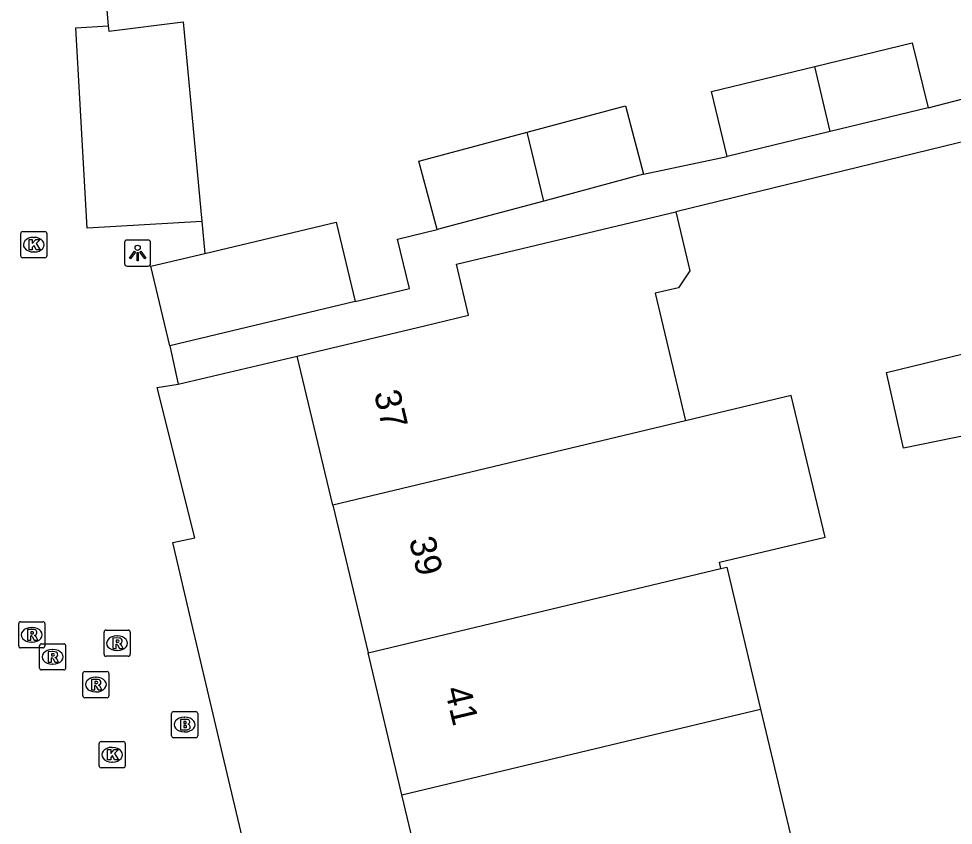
# Model space of a CAD drawing. Extents: x 158038 to 159242, y 380133 to 381214.
# Drawn here: x 158439.3 to 158475.04, y 381055.11 to 381085.97 of the extents above; entities that cross this region are included whole.
import ezdxf

# ---------------------------------------------------------------- set-up
doc = ezdxf.new("R2010")
doc.units = 0
for name, color, linetype in [('IMGEO_Brandkraan', 7, 'Continuous'), ('IMGEO_Kolk', 7, 'Continuous'), ('IMGEO_Lichtpunt', 7, 'Continuous'), ('IMGEO_Pand', 7, 'Continuous'), ('IMGEO_Pand_nummerreeks', 7, 'Continuous'), ('IMGEO_Parkeervlak_open', 7, 'Continuous'), ('IMGEO_Rioolput', 7, 'Continuous'), ('IMGEO_Voetpad_open', 7, 'Continuous')]:
    doc.layers.add(name, color=color, linetype=linetype)

msp = doc.modelspace()

# ---------------------------------------------------------------- linework, layer by layer
at = {"layer": 'IMGEO_Brandkraan'}
for p, q in [((158445.141, 381058.539), (158445.141, 381059.391)), ((158445.216, 381059.465), (158446.068, 381059.465)), ((158445.629, 381059.245), (158445.654, 381059.245)), ((158446.142, 381059.391), (158446.142, 381058.539)), ((158446.068, 381058.465), (158445.216, 381058.465)), ((158445.652, 381058.685), (158445.627, 381058.685))]:
    msp.add_line(p, q, dxfattribs=at)
for points in [[(158445.141, 381058.539), (158445.141, 381059.391)], [(158445.216, 381059.465), (158446.068, 381059.465)], [(158446.142, 381059.391), (158446.142, 381058.539)], [(158445.489, 381059.165), (158445.489, 381058.765), (158445.702, 381058.765)], [(158445.72, 381059.165), (158445.489, 381059.165)], [(158445.668, 381059.084), (158445.614, 381059.084), (158445.614, 381059.008)], [(158445.614, 381059.008), (158445.667, 381059.008)], [(158445.676, 381058.932), (158445.614, 381058.932), (158445.614, 381058.851)], [(158445.614, 381058.851), (158445.676, 381058.851)], [(158446.068, 381058.465), (158445.216, 381058.465)]]:
    msp.add_lwpolyline(points, dxfattribs=at)
for centre, radius, start, end in [((158445.218, 381059.389), 0.0765, 91.552, 178.448), ((158445.218, 381059.389), 0.0765, 91.552, 178.448), ((158446.066, 381059.389), 0.0765, 1.552, 88.448), ((158446.066, 381059.389), 0.0765, 1.552, 88.448), ((158445.669, 381059.046), 0.0379, 267.8285, 90.9355), ((158445.677, 381058.891), 0.0404, 269.8759, 90.5077), ((158445.724, 381059.02), 0.145, 59.4692, 91.5367), ((158445.749, 381059.067), 0.0922, 285.5137, 58.1501), ((158445.754, 381058.875), 0.105, 301.3115, 78.989), ((158445.218, 381058.541), 0.0765, 181.552, 268.448), ((158445.218, 381058.541), 0.0765, 181.552, 268.448), ((158445.708, 381059.016), 0.251, 268.6676, 293.5347), ((158446.066, 381058.541), 0.0765, 271.552, 358.448), ((158446.066, 381058.541), 0.0765, 271.552, 358.448)]:
    msp.add_arc(centre, radius, start, end, dxfattribs=at)
for centre, major_axis, ratio, start_param, end_param in [((158445.628, 381058.965), (-0.387, 0.002), 0.722429, 4.712389, 7.853982), ((158445.653, 381058.965), (-0.39, 0.002), 0.717154, 1.570796, 4.712389)]:
    msp.add_ellipse(centre, major_axis=major_axis, ratio=ratio, start_param=start_param, end_param=end_param, dxfattribs=at)
at = {"layer": 'IMGEO_Kolk'}
for p, q in [((158439.448, 381077.824), (158440.3, 381077.824)), ((158439.373, 381076.898), (158439.373, 381077.75)), ((158439.861, 381077.604), (158439.886, 381077.604)), ((158440.374, 381077.75), (158440.374, 381076.898)), ((158439.884, 381077.044), (158439.859, 381077.044)), ((158440.3, 381076.824), (158439.448, 381076.824)), ((158442.37, 381057.388), (158442.37, 381058.24)), ((158442.445, 381058.314), (158443.297, 381058.314)), ((158443.371, 381058.24), (158443.371, 381057.388)), ((158442.858, 381058.094), (158442.883, 381058.094)), ((158442.881, 381057.534), (158442.856, 381057.534)), ((158443.297, 381057.314), (158442.445, 381057.314))]:
    msp.add_line(p, q, dxfattribs=at)
for points in [[(158439.448, 381077.824), (158440.3, 381077.824)], [(158439.373, 381076.898), (158439.373, 381077.75)], [(158439.694, 381077.524), (158439.817, 381077.524), (158439.817, 381077.373), (158439.947, 381077.524), (158440.111, 381077.524), (158439.965, 381077.373), (158440.118, 381077.124), (158439.966, 381077.124), (158439.881, 381077.288), (158439.817, 381077.221), (158439.817, 381077.124), (158439.694, 381077.124), (158439.694, 381077.524)], [(158440.374, 381077.75), (158440.374, 381076.898)], [(158440.3, 381076.824), (158439.448, 381076.824)], [(158442.37, 381057.388), (158442.37, 381058.24)], [(158442.445, 381058.314), (158443.297, 381058.314)], [(158443.371, 381058.24), (158443.371, 381057.388)], [(158442.691, 381058.014), (158442.814, 381058.014), (158442.814, 381057.863), (158442.944, 381058.014), (158443.108, 381058.014), (158442.962, 381057.863), (158443.115, 381057.614), (158442.963, 381057.614), (158442.878, 381057.778), (158442.814, 381057.711), (158442.814, 381057.614), (158442.691, 381057.614), (158442.691, 381058.014)], [(158443.297, 381057.314), (158442.445, 381057.314)]]:
    msp.add_lwpolyline(points, dxfattribs=at)
for centre, start, end in [((158439.45, 381077.748), 91.552, 178.448), ((158439.45, 381077.748), 91.552, 178.448), ((158440.298, 381077.748), 1.552, 88.448), ((158440.298, 381077.748), 1.552, 88.448), ((158439.45, 381076.9), 181.552, 268.448), ((158439.45, 381076.9), 181.552, 268.448), ((158440.298, 381076.9), 271.552, 358.448), ((158440.298, 381076.9), 271.552, 358.448), ((158442.447, 381058.238), 91.552, 178.448), ((158442.447, 381058.238), 91.552, 178.448), ((158443.295, 381058.238), 1.552, 88.448), ((158443.295, 381058.238), 1.552, 88.448), ((158442.447, 381057.39), 181.552, 268.448), ((158442.447, 381057.39), 181.552, 268.448), ((158443.295, 381057.39), 271.552, 358.448), ((158443.295, 381057.39), 271.552, 358.448)]:
    msp.add_arc(centre, 0.0765, start, end, dxfattribs=at)
for centre, major_axis, ratio, start_param, end_param in [((158439.86, 381077.324), (-0.387, 0.002), 0.722429, 4.712389, 7.853982), ((158439.885, 381077.324), (-0.39, 0.002), 0.717154, 1.570796, 4.712389), ((158442.857, 381057.814), (-0.387, 0.002), 0.722429, 4.712389, 7.853982), ((158442.882, 381057.814), (-0.39, 0.002), 0.717154, 1.570796, 4.712389)]:
    msp.add_ellipse(centre, major_axis=major_axis, ratio=ratio, start_param=start_param, end_param=end_param, dxfattribs=at)
at = {"layer": 'IMGEO_Lichtpunt'}
for p, q in [((158443.346, 381077.407), (158443.346, 381076.6)), ((158443.346, 381077.407), (158443.346, 381076.6)), ((158444.248, 381077.502), (158443.44, 381077.502)), ((158444.248, 381077.502), (158443.44, 381077.502)), ((158444.342, 381076.6), (158444.342, 381077.407)), ((158444.342, 381076.6), (158444.342, 381077.407)), ((158443.44, 381076.506), (158444.248, 381076.506)), ((158443.44, 381076.506), (158444.248, 381076.506))]:
    msp.add_line(p, q, dxfattribs=at)
for points in [[(158443.72, 381077.071), (158443.759, 381077.043), (158443.571, 381076.781), (158443.533, 381076.808), (158443.72, 381077.071)], [(158443.932, 381077.043), (158443.97, 381077.07), (158444.157, 381076.808), (158444.118, 381076.78), (158443.932, 381077.043)], [(158443.822, 381077.023), (158443.869, 381077.023), (158443.869, 381076.701), (158443.822, 381076.701), (158443.822, 381077.023)]]:
    msp.add_lwpolyline(points, dxfattribs=at)
msp.add_circle((158443.845, 381077.205), 0.0994, dxfattribs=at)
for centre, start, end in [((158443.44, 381077.407), 90, 180), ((158443.44, 381077.407), 90, 180), ((158444.248, 381077.407), 0, 90), ((158444.248, 381077.407), 0, 90), ((158443.44, 381076.6), 180, 270), ((158443.44, 381076.6), 180, 270), ((158444.248, 381076.6), 270, 0), ((158444.248, 381076.6), 270, 360)]:
    msp.add_arc(centre, 0.0946, start, end, dxfattribs=at)
at = {"layer": 'IMGEO_Pand'}
for points in [[(158469.74, 381084.142), (158473.474, 381085.047), (158474.077, 381082.564)], [(158466.391, 381080.7), (158465.789, 381083.183), (158469.74, 381084.142)], [(158470.334, 381081.656), (158469.74, 381084.142)], [(158458.745, 381081.625), (158462.498, 381082.631), (158463.199, 381080.018)], [(158474.077, 381082.564), (158470.334, 381081.656)], [(158455.306, 381077.901), (158454.605, 381080.514), (158458.745, 381081.625)], [(158459.375, 381078.993), (158458.745, 381081.625)], [(158470.334, 381081.656), (158466.391, 381080.7)], [(158463.199, 381080.018), (158459.375, 381078.993)], [(158459.375, 381078.993), (158455.306, 381077.901)], [(158449.949, 381073.061), (158454.813, 381074.222), (158456.505, 381074.626), (158456.038, 381076.581), (158464.428, 381078.584)], [(158464.428, 381078.584), (158464.968, 381076.318), (158464.527, 381075.676), (158463.639, 381075.464), (158464.804, 381070.586)], [(158446.413, 381076.99), (158451.439, 381078.19), (158452.165, 381075.147)], [(158445.073, 381073.454), (158444.346, 381076.497), (158446.413, 381076.99)], [(158452.165, 381075.147), (158445.073, 381073.454)], [(158479.975, 381069.848), (158477.836, 381069.413), (158477.569, 381070.449), (158473.135, 381069.546), (158472.493, 381072.44), (158476.891, 381073.501)], [(158451.311, 381067.355), (158449.949, 381073.061)], [(158466.154, 381064.935), (158466.096, 381065.176), (158470.135, 381066.141), (158468.842, 381071.553), (158464.804, 381070.586)], [(158464.804, 381070.586), (158451.311, 381067.355)], [(158451.311, 381067.355), (158452.657, 381061.714)], [(158452.657, 381061.714), (158466.154, 381064.935)], [(158466.154, 381064.935), (158466.377, 381064.988), (158467.674, 381059.556)], [(158453.954, 381056.282), (158452.657, 381061.714)], [(158453.954, 381056.282), (158462.534, 381058.328), (158467.674, 381059.556)], [(158467.674, 381059.556), (158469.024, 381053.9)], [(158457.583, 381051.17), (158455.304, 381050.627), (158453.954, 381056.282)]]:
    msp.add_lwpolyline(points, dxfattribs=at)
at = {"layer": 'IMGEO_Parkeervlak_open'}
msp.add_lwpolyline([(158442.724, 381085.689), (158442.741, 381085.485), (158445.587, 381085.853), (158446.299, 381078.211)], dxfattribs=at)
at = {"layer": 'IMGEO_Rioolput'}
for p, q in [((158439.295, 381061.975), (158439.295, 381062.827)), ((158439.37, 381062.901), (158440.222, 381062.901)), ((158440.296, 381062.827), (158440.296, 381061.975)), ((158439.783, 381062.681), (158439.808, 381062.681)), ((158442.56, 381061.654), (158442.56, 381062.506)), ((158442.635, 381062.58), (158443.487, 381062.58)), ((158443.561, 381062.506), (158443.561, 381061.654)), ((158439.806, 381062.121), (158439.781, 381062.121)), ((158440.166, 381062.056), (158441.018, 381062.056)), ((158443.048, 381062.36), (158443.073, 381062.36)), ((158440.222, 381061.901), (158439.37, 381061.901)), ((158440.091, 381061.13), (158440.091, 381061.982)), ((158440.579, 381061.836), (158440.604, 381061.836)), ((158441.092, 381061.982), (158441.092, 381061.13)), ((158443.071, 381061.8), (158443.046, 381061.8)), ((158443.487, 381061.58), (158442.635, 381061.58)), ((158441.018, 381061.056), (158440.166, 381061.056)), ((158440.602, 381061.276), (158440.577, 381061.276)), ((158441.821, 381060.996), (158442.673, 381060.996)), ((158441.746, 381060.07), (158441.746, 381060.922)), ((158442.234, 381060.776), (158442.259, 381060.776)), ((158442.747, 381060.922), (158442.747, 381060.07)), ((158442.673, 381059.996), (158441.821, 381059.996)), ((158442.257, 381060.216), (158442.232, 381060.216))]:
    msp.add_line(p, q, dxfattribs=at)
for points in [[(158439.295, 381061.975), (158439.295, 381062.827)], [(158439.37, 381062.901), (158440.222, 381062.901)], [(158440.296, 381062.827), (158440.296, 381061.975)], [(158439.884, 381062.599), (158439.632, 381062.601), (158439.632, 381062.201)], [(158439.81, 381062.52), (158439.756, 381062.52), (158439.756, 381062.439)], [(158439.756, 381062.439), (158439.808, 381062.439)], [(158442.56, 381061.654), (158442.56, 381062.506)], [(158442.635, 381062.58), (158443.487, 381062.58)], [(158443.561, 381062.506), (158443.561, 381061.654)], [(158439.632, 381062.201), (158439.756, 381062.201), (158439.756, 381062.363), (158439.767, 381062.363)], [(158439.814, 381062.334), (158439.885, 381062.201), (158440.025, 381062.201), (158439.96, 381062.327)], [(158440.166, 381062.056), (158441.018, 381062.056)], [(158443.149, 381062.278), (158442.897, 381062.28), (158442.897, 381061.88)], [(158442.897, 381061.88), (158443.021, 381061.88), (158443.021, 381062.042), (158443.032, 381062.042)], [(158443.075, 381062.199), (158443.021, 381062.199), (158443.021, 381062.118)], [(158443.021, 381062.118), (158443.073, 381062.118)], [(158440.222, 381061.901), (158439.37, 381061.901)], [(158440.091, 381061.13), (158440.091, 381061.982)], [(158440.68, 381061.754), (158440.428, 381061.756), (158440.428, 381061.356)], [(158440.606, 381061.675), (158440.552, 381061.675), (158440.552, 381061.594)], [(158441.092, 381061.982), (158441.092, 381061.13)], [(158443.079, 381062.013), (158443.15, 381061.88), (158443.29, 381061.88), (158443.225, 381062.006)], [(158440.428, 381061.356), (158440.552, 381061.356), (158440.552, 381061.518), (158440.563, 381061.518)], [(158440.552, 381061.594), (158440.604, 381061.594)], [(158440.61, 381061.489), (158440.681, 381061.356), (158440.821, 381061.356), (158440.756, 381061.482)], [(158443.487, 381061.58), (158442.635, 381061.58)], [(158441.018, 381061.056), (158440.166, 381061.056)], [(158441.821, 381060.996), (158442.673, 381060.996)], [(158441.746, 381060.07), (158441.746, 381060.922)], [(158442.335, 381060.694), (158442.083, 381060.696), (158442.083, 381060.296)], [(158442.261, 381060.615), (158442.207, 381060.615), (158442.207, 381060.534)], [(158442.747, 381060.922), (158442.747, 381060.07)], [(158442.083, 381060.296), (158442.207, 381060.296), (158442.207, 381060.458), (158442.218, 381060.458)], [(158442.207, 381060.534), (158442.259, 381060.534)], [(158442.265, 381060.429), (158442.336, 381060.296), (158442.476, 381060.296), (158442.411, 381060.422)], [(158442.673, 381059.996), (158441.821, 381059.996)]]:
    msp.add_lwpolyline(points, dxfattribs=at)
for centre, radius, start, end in [((158439.372, 381062.825), 0.0765, 91.552, 178.448), ((158439.372, 381062.825), 0.0765, 91.552, 178.448), ((158440.22, 381062.825), 0.0765, 1.552, 88.448), ((158440.22, 381062.825), 0.0765, 1.552, 88.448), ((158439.792, 381062.628), 0.19, 274.7715, 282.9687), ((158439.816, 381062.424), 0.0964, 77.0061, 93.1865), ((158439.83, 381062.481), 0.0378, 276.6634, 79.6772), ((158439.883, 381062.489), 0.109, 350.3612, 89.416), ((158439.881, 381062.489), 0.112, 277.5842, 350.9817), ((158442.637, 381062.504), 0.0765, 91.552, 178.448), ((158442.637, 381062.504), 0.0765, 91.552, 178.448), ((158443.485, 381062.504), 0.0765, 1.552, 88.448), ((158443.485, 381062.504), 0.0765, 1.552, 88.448), ((158439.766, 381062.31), 0.0533, 26.0293, 88.6989), ((158439.865, 381062.274), 0.108, 29.5134, 73.7905), ((158440.168, 381061.98), 0.0765, 91.552, 178.448), ((158440.168, 381061.98), 0.0765, 91.552, 178.448), ((158441.016, 381061.98), 0.0765, 1.552, 88.448), ((158441.016, 381061.98), 0.0765, 1.552, 88.448), ((158443.031, 381061.989), 0.0533, 26.0293, 88.6989), ((158443.057, 381062.307), 0.19, 274.7715, 282.9687), ((158443.081, 381062.103), 0.0964, 77.0061, 93.1865), ((158443.095, 381062.16), 0.0378, 276.6634, 79.6772), ((158443.148, 381062.168), 0.109, 350.3612, 89.416), ((158443.146, 381062.168), 0.112, 277.5842, 350.9817), ((158443.13, 381061.953), 0.108, 29.5134, 73.7905), ((158439.372, 381061.977), 0.0765, 181.552, 268.448), ((158439.372, 381061.977), 0.0765, 181.552, 268.448), ((158440.22, 381061.977), 0.0765, 271.552, 358.448), ((158440.22, 381061.977), 0.0765, 271.552, 358.448), ((158440.612, 381061.579), 0.0964, 77.0061, 93.1865), ((158440.626, 381061.636), 0.0378, 276.6634, 79.6772), ((158440.679, 381061.644), 0.109, 350.3612, 89.416), ((158440.562, 381061.465), 0.0533, 26.0293, 88.6989), ((158440.588, 381061.783), 0.19, 274.7715, 282.9687), ((158440.677, 381061.644), 0.112, 277.5842, 350.9817), ((158440.661, 381061.429), 0.108, 29.5134, 73.7905), ((158442.637, 381061.656), 0.0765, 181.552, 268.448), ((158442.637, 381061.656), 0.0765, 181.552, 268.448), ((158443.485, 381061.656), 0.0765, 271.552, 358.448), ((158443.485, 381061.656), 0.0765, 271.552, 358.448), ((158440.168, 381061.132), 0.0765, 181.552, 268.448), ((158440.168, 381061.132), 0.0765, 181.552, 268.448), ((158441.016, 381061.132), 0.0765, 271.552, 358.448), ((158441.016, 381061.132), 0.0765, 271.552, 358.448), ((158441.823, 381060.92), 0.0765, 91.552, 178.448), ((158441.823, 381060.92), 0.0765, 91.552, 178.448), ((158442.671, 381060.92), 0.0765, 1.552, 88.448), ((158442.671, 381060.92), 0.0765, 1.552, 88.448), ((158442.267, 381060.519), 0.0964, 77.0061, 93.1865), ((158442.281, 381060.576), 0.0378, 276.6634, 79.6772), ((158442.334, 381060.584), 0.109, 350.3612, 89.416), ((158442.217, 381060.405), 0.0533, 26.0293, 88.6989), ((158442.243, 381060.723), 0.19, 274.7715, 282.9687), ((158442.332, 381060.584), 0.112, 277.5842, 350.9817), ((158442.316, 381060.369), 0.108, 29.5134, 73.7905), ((158441.823, 381060.072), 0.0765, 181.552, 268.448), ((158441.823, 381060.072), 0.0765, 181.552, 268.448), ((158442.671, 381060.072), 0.0765, 271.552, 358.448), ((158442.671, 381060.072), 0.0765, 271.552, 358.448)]:
    msp.add_arc(centre, radius, start, end, dxfattribs=at)
for centre, major_axis, ratio, start_param, end_param in [((158439.782, 381062.401), (-0.387, 0.002), 0.722429, 4.712389, 7.853982), ((158439.807, 381062.401), (-0.39, 0.002), 0.717154, 1.570796, 4.712389), ((158443.047, 381062.08), (-0.387, 0.002), 0.722429, 4.712389, 7.853982), ((158443.072, 381062.08), (-0.39, 0.002), 0.717154, 1.570796, 4.712389), ((158440.578, 381061.556), (-0.387, 0.002), 0.722429, 4.712389, 7.853982), ((158440.603, 381061.556), (-0.39, 0.002), 0.717154, 1.570796, 4.712389), ((158442.233, 381060.496), (-0.387, 0.002), 0.722429, 4.712389, 7.853982), ((158442.258, 381060.496), (-0.39, 0.002), 0.717154, 1.570796, 4.712389)]:
    msp.add_ellipse(centre, major_axis=major_axis, ratio=ratio, start_param=start_param, end_param=end_param, dxfattribs=at)
at = {"layer": 'IMGEO_Voetpad_open'}
for points in [[(158483.543, 381112.187), (158480.679, 381111.494), (158480.858, 381110.722), (158477.995, 381110.041), (158470.208, 381108.189), (158469.945, 381109.353), (158464.345, 381108.005), (158464.06, 381109.04), (158447.187, 381105.029), (158447.507, 381103.594), (158441.352, 381101.994), (158442.724, 381085.689)], [(158446.299, 381078.211), (158441.919, 381077.961), (158441.481, 381085.619), (158442.724, 381085.689)], [(158474.077, 381082.564), (158477.573, 381083.462)], [(158478.123, 381078.19), (158477.337, 381081.733), (158464.428, 381078.584)], [(158463.199, 381080.018), (158466.391, 381080.7)], [(158446.299, 381078.211), (158446.413, 381076.99)], [(158452.165, 381075.147), (158454.243, 381075.643), (158453.785, 381077.532), (158455.306, 381077.901)], [(158445.073, 381073.454), (158445.397, 381071.992)], [(158445.397, 381071.992), (158449.949, 381073.061)], [(158457.904, 381027.768), (158457.268, 381030.374), (158456.56, 381033.275), (158455.688, 381033.178), (158451.746, 381049.535), (158449.198, 381048.972), (158447.16, 381057.585), (158445.882, 381062.985), (158445.185, 381065.93), (158446.037, 381066.108), (158444.595, 381071.862), (158445.397, 381071.992)]]:
    msp.add_lwpolyline(points, dxfattribs=at)

# ---------------------------------------------------------------- texts
at = {"layer": 'IMGEO_Pand_nummerreeks'}
for s, rotation, p in [('37', 283.4242, (158452.878, 381071.645)), ('39', 283.4242, (158454.217, 381066.036)), ('41', 283.4247, (158455.582, 381060.318))]:
    msp.add_text(s, height=1, rotation=rotation, dxfattribs=at).set_placement(p)

doc.saveas('drawing.dxf')
